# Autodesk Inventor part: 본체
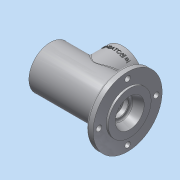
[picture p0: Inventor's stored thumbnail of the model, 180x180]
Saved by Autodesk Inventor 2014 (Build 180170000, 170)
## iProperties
Created: 2016-08
Part Number: 본체
Material: 알루미늄 6061
Document SubType Name: Modeling
Designer: 402-003
Density: 2.71 g/cm^3
Appearance: 알루미늄 - 평지
Author: 402-003
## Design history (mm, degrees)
sketch "스케치5"
  geometry: C1 r 50 at (0, 0); 1 further point
  constraints: 1 centre point, 1 coincident
  dimensions: "d6" = 100 diameter of C1
extrude "돌출3" new body sketch "스케치5" distance "d7" = 10; taper "d8" = 0 deg
sketch "스케치6"
  geometry: C1 r 50 at (0, 0) reference; C2 r 31 at (0, 0)
  constraints: 1 centre point, 1 coincident
  dimensions: "d9" = 62 diameter of C2
extrude "돌출4" join sketch "스케치6" distance "d10" = 3; taper "d11" = 0 deg
sketch "스케치7"
  geometry: C1 r 50 at (0, 0) reference; C2 r 31 at (0, 0)
  constraints: 1 centre point, 1 coincident
  dimensions: "d12" = 62 diameter of C2
extrude "돌출5" join sketch "스케치7" distance "d13" = 102; taper "d14" = 0 deg
sketch "스케치8"
  geometry: L1 (3, 0)-(-103, 0); L2 (-112, 31)-(-112, -31) reference; L3 (3, -31)-(3, 31) reference; L4 (-103, 0)-(-103, 24); L5 (-103, 24)-(-100, 24); L6 (-100, 24)-(-100, 20); L7 (-100, 20)-(-91, 20); L8 (-91, 20)-(-91, 17.5); L9 (-91, 17.5)-(-86, 17.5); L10 (-86, 17.5)-(-86, 18.5); L11 (-86, 18.5)-(-84.25, 18.5); L12 (-84.25, 18.5)-(-84.25, 17.5); L13 (-11, 12.904)-(-11, 13.886); L14 (-9.009, 16.711)-(3, 21); L15 (-11.7, 12.5)-(-11, 12.904); L16 (-11.7, 12.5)-(-18, 12.5); L17 (-18.3, 12.2)-(-18.3, 10); L18 (-18.3, 10)-(-21, 10); L19 (-24.25, 17.2)-(-24.25, 16.5); L20 (-24.25, 16.5)-(-24, 16.5); L21 (-21, 13.5)-(-21, 10); L22 (3, 21)-(3, 0); L23 (-75, 26)-(-37, 26); L24 (-37, 26)-(-37, 17.5); L25 (-75, 17.5)-(-75, 26); L26 (-84.25, 17.5)-(-75, 17.5); L27 (-37, 17.5)-(-24.55, 17.5); A1 r 0.3 centre (-18, 12.2) between (-18, 12.5) and (-18.3, 12.2); A2 r 3 centre (-24, 13.5) between (-21, 13.5) and (-24, 16.5); A3 r 3 centre (-8, 13.886) between (-9.009, 16.711) and (-11, 13.886); A4 r 0.3 centre (-24.55, 17.2) between (-24.25, 17.2) and (-24.55, 17.5); 5 further points
  constraints: 50 end point, 15 parallel, 8 point on circle, 8 tangent, 7 point on line, 6 perpendicular, 4 centre point, 2 horizontal, 2 midpoint, 2 vertical, 1 collinear
  dimensions: "d15" = 48 diameter of L5 L1; "d16" = 3 distance of L4.end L5.end; "d17" = 40 diameter of L7 L1; "d18" = 35 diameter of L9 L1; "d19" = 37 diameter of L11 L1; "d20" = 1.75 distance of L10.end L11.end; "d21" = 17 distance from line of L4 L10.end; "d23" = 42 diameter of L14.end L1; "d24" = 32 diameter of point (-11, 16) L1; "d25" = 0.7 horizontal distance of L13.start L15.start; "d26" = 7.3 horizontal distance of point (-18.3, 12.5) L13.start; "d27" = 25 diameter of L16 L1; "d28" = 2.7 distance of L18.end L17.end; "d29" = 20 diameter of L18 L1; "d30" = 30 deg angle of L16 L15; "d31" = 0.3 radius of A1; "d32" = 14 horizontal distance of point (-11, 16) L14.end; "d33" = 33 diameter of L20 L1; "d36" = 3 radius of A2; "d37" = 9 distance of L6.end L7.end; "d38" = 9 distance between parallel lines of L2 L4; "d60" = 52 diameter of L23 L1; "d61" = 60 distance between parallel lines of L19 L12; "d62" = 35 diameter of L27 L1; "d63" = 38 distance of L23.start L23.end; "d64" = 56 distance from line of L2 point (-56, 26); "d96" = 3 radius of A3; "d97" = 0.3 radius of A4
revolve "회전1" sketch "스케치8" stored, may be unused: angle "d45" = 90 deg
hole "구멍1" diameter "d48" = 40.376; stored, may be unused: countersink angle "d52" = 90 deg, drill point angle "d54" = 118 deg; dims "d46" = 10, "d47" = 10, "d49" = 9, "d50" = 4, "d51" = 2, "d53" = 9
node "작업 평면1"
sketch "스케치9"
  geometry: L1 (112, -31)-(112, 31) reference; C1 r 30 at (56, 0); 1 further point
  constraints: 1 centre point, 1 horizontal alignment
  dimensions: "d56" = 60 diameter of C1; "d57" = 56 distance from line of L1 C1.centre
extrude "돌출6" join sketch "스케치9" stored distance "d58" = 102; taper "d59" = 0 deg
hole "구멍2" diameter "d67" = 38; stored, may be unused: countersink angle "d71" = 90 deg, drill point angle "d73" = 118 deg; dims "d65" = 10, "d66" = 10, "d68" = 9, "d69" = 4, "d70" = 2, "d72" = 9
sketch "스케치10" dims "d74" = 48
  geometry: C1 r 19 at (0, 0) reference; C2 r 30 at (0, 0) reference; 3 further points
  constraints: 2 vertical alignment, 1 coincident, 2 other
hole "구멍3" sketch "스케치10" at (0, 24) diameter "d75" = 3.242; stored, may be unused: countersink angle "d79" = 90 deg, drill point angle "d81" = 118 deg; dims "d76" = 8, "d77" = 4, "d78" = 2, "d80" = 10
sketch "스케치11" dims "d85" = 83
  geometry: C1 r 31 at (0, 0) reference; 2 further points
  constraints: 2 vertical alignment, 1 coincident, 2 other
hole "구멍4" sketch "스케치11" at (0, 41.5) diameter "d86" = 8; stored, may be unused: countersink angle "d90" = 90 deg, drill point angle "d92" = 118 deg; dims "d87" = 8, "d88" = 4, "d89" = 2, "d91" = 10
fillet "모깎기1" dims "d98" = 3
fillet "모깎기2" dims "d99" = 3
node "작업 평면2"
sketch "스케치12"
  geometry: L1 (-56, -18)-(-56, -80) reference; L2 (-30, 0)-(30, 0) reference; 2 further points
  constraints: 1 other
  dimensions: "d100" = 56 distance from line of L1 point (0, -10); "d101" = 10 distance from line of L2 point (0, -10)
feature "엠보싱1" sketch "스케치12" dims "d102" = 0.5, "d103" = 0
chamfer "모따기1" distance "d104" = 1; stored, may be unused: second distance "d105" = 2, angle "d106" = 45 deg
node "솔리드3"
pattern_circular "원형 패턴1" dims angle "d83" = 360 deg
pattern_circular "원형 패턴2" dims angle "d94" = 360 deg
other parameters: "d34" = 35, "d55" = 49
